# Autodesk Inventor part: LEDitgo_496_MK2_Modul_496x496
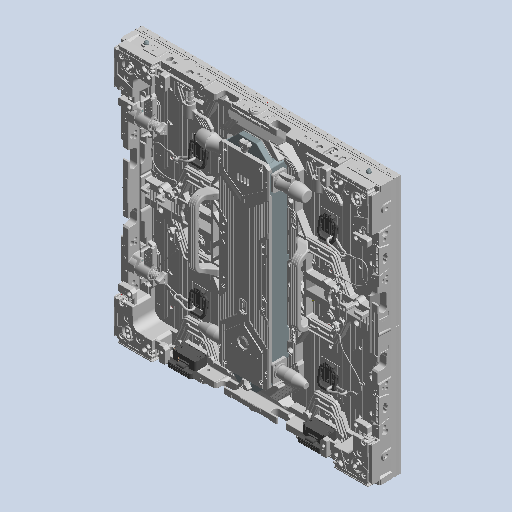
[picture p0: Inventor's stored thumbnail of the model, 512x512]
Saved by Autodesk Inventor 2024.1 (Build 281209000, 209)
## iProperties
Company: LEDitgo Videowall Germany GmbH
Created: 2024-11
Part Number: LEDitgo_496_MK2_Modul_496x496
Material: Allgemein
Document SubType Name: Modellieren
Designer: Tobias Jandausch
Appearance: Klar - hell
Project: 496 MK2 Serie
Description: 496 MK2 Modul 496x496
Sending System: SIEMENS PLM Software NX 12.0
Preprocessor: ST-DEVELOPER v16.7
Title: LEDitgo_496_MK2_Modul_496x496
Revision Number: 01
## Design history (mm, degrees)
feature "DK" [Basis]
feature "Basis2"
feature "DYH-H" [Basis]
feature "Basis4"
feature "Basis5"
feature "DK:1" [Basis]
feature "Basis7"
feature "DK:2" [Basis]
feature "Basis9"
feature "Basis10"
feature "Basis11"
feature "Basis12"
feature "DK:3" [Basis]
feature "Basis14"
feature "KM4X20" [Basis]
feature "KM4X20:1" [Basis]
feature "KM4X20:2" [Basis]
feature "KM4X20:3" [Basis]
feature "KM4X20:4" [Basis]
feature "KM4X20:5" [Basis]
feature "Basis21"
feature "Basis22"
feature "Basis23"
feature "Basis24"
feature "KM4X20:6" [Basis]
feature "KM4X20:7" [Basis]
feature "KM4X20:8" [Basis]
feature "Basis28"
feature "Basis29"
feature "KM4X20:9" [Basis]
feature "KM4X20:10" [Basis]
feature "KM4X20:11" [Basis]
feature "Basis33"
feature "Basis34"
feature "Basis35"
feature "Basis36"
feature "Basis37"
feature "Basis38"
node "Volumenkörper1"
node "Volumenkörper"
node "Flächenkörper"
node "Volumenkörper18"
node "Volumenkörper2"
node "Volumenkörper19"
node "Volumenkörper20"
node "Volumenkörper3"
node "Volumenkörper21"
node "Volumenkörper4"
node "Volumenkörper22"
node "Volumenkörper23"
node "Volumenkörper24"
node "Volumenkörper25"
node "Volumenkörper5"
node "Volumenkörper26"
node "Volumenkörper6"
node "Volumenkörper7"
node "Volumenkörper8"
node "Volumenkörper9"
node "Volumenkörper10"
node "Volumenkörper11"
node "Volumenkörper27"
node "Volumenkörper28"
node "Volumenkörper29"
node "Volumenkörper30"
node "Volumenkörper12"
node "Volumenkörper13"
node "Volumenkörper14"
node "Volumenkörper31"
node "Volumenkörper32"
node "Volumenkörper15"
node "Volumenkörper16"
node "Volumenkörper17"
node "Volumenkörper33"
node "Volumenkörper34"
node "Volumenkörper35"
node "Volumenkörper36"
node "Volumenkörper37"
node "Volumenkörper38"
